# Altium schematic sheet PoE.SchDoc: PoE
size A4; CompanyName: STMicroelectronics; Organization: Microcontrollers Division; DocumentNumber: 13; SheetNumber: 6; SheetTotal: 19
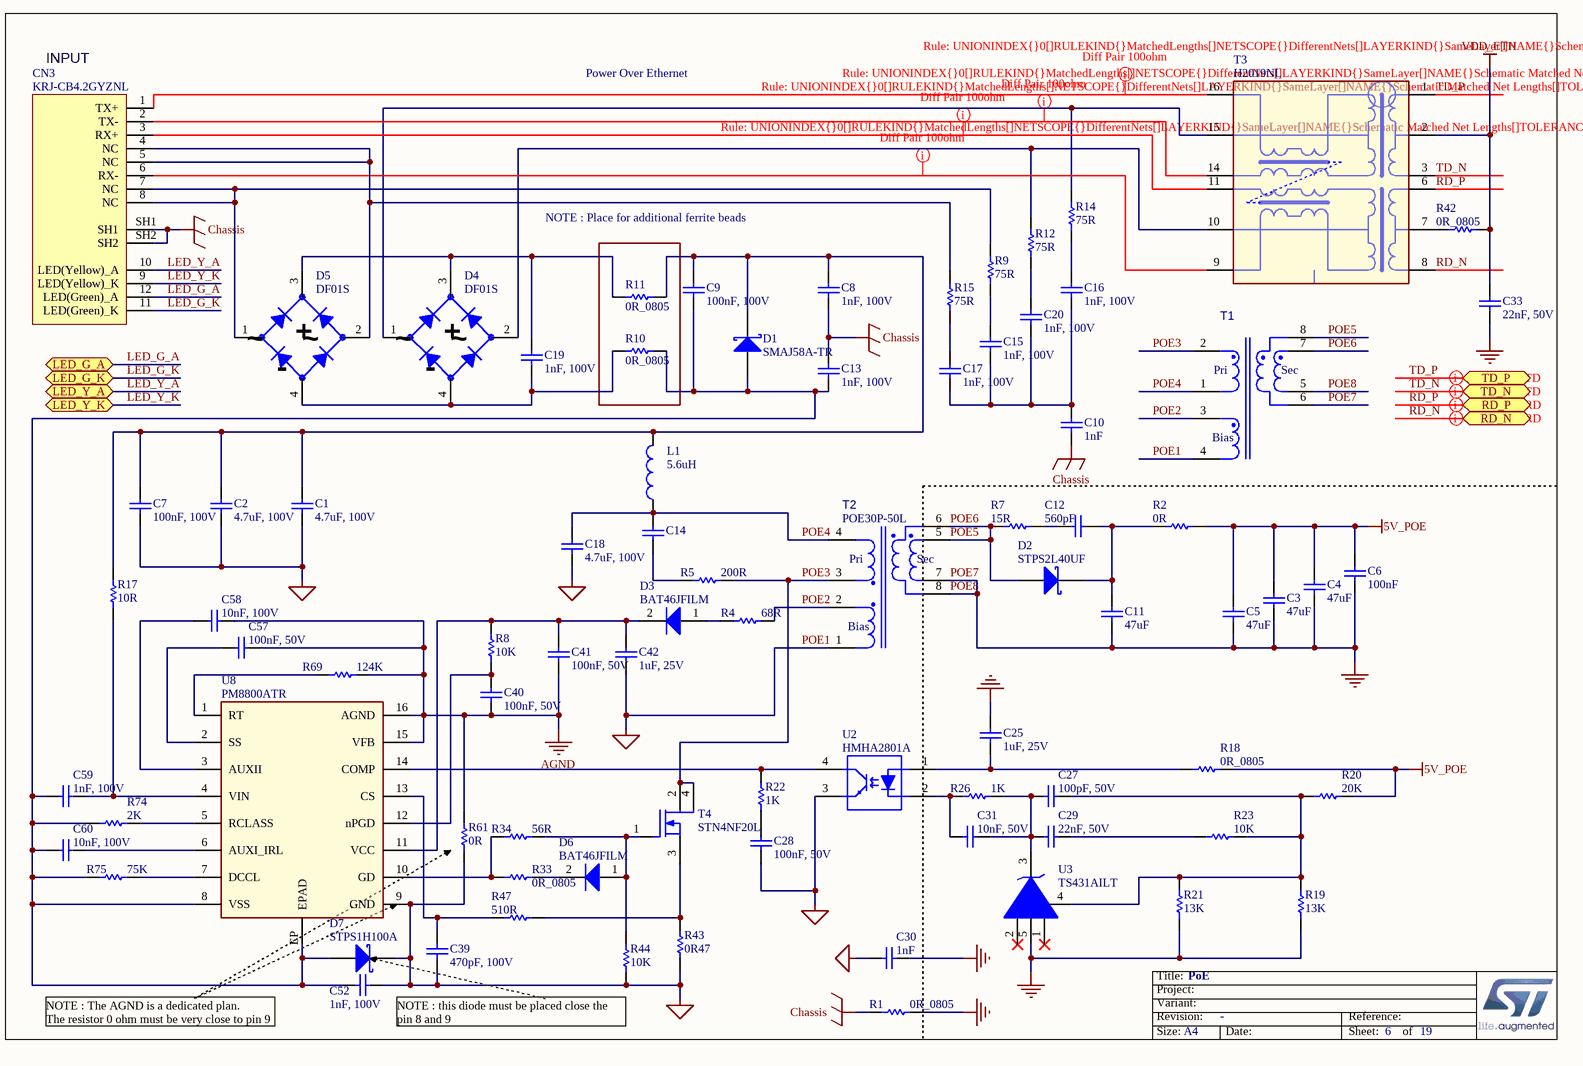
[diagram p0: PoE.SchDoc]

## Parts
C1  value 4.7uF, 100V  [C1210]  (hidden comment: Capacitor)
C2  value 4.7uF, 100V  [C1210]  (hidden comment: Capacitor)
C3  value 47uF  [C0805]  (hidden comment: Capacitor)
C4  value 47uF  [C0805]  (hidden comment: Capacitor)
C5  value 47uF  [C0805]  (hidden comment: Capacitor)
C6  value 100nF  [C0603]  (hidden comment: Capacitor)
C7  value 100nF, 100V  [C0805]  (hidden comment: Capacitor)
C8  value 1nF, 100V  [C0603]  (hidden comment: Capacitor)
C9  value 100nF, 100V  [C0805]  (hidden comment: Capacitor)
C10  value 1nF  [C1206_H1P6]  (hidden comment: Capacitor)
C11  value 47uF  [C0805]  (hidden comment: Capacitor)
C12  value 560pF  [C0603]  (hidden comment: Capacitor)
C13  value 1nF, 100V  [C0603]  (hidden comment: Capacitor)
C14  Capacitor  [C0603]  (value not drawn)
C15  value 1nF, 100V  [C0603]  (hidden comment: Capacitor)
C16  value 1nF, 100V  [C0603]  (hidden comment: Capacitor)
C17  value 1nF, 100V  [C0603]  (hidden comment: Capacitor)
C18  value 4.7uF, 100V  [C1210]  (hidden comment: Capacitor)
C19  value 1nF, 100V  [C0603]  (hidden comment: Capacitor)
C20  value 1nF, 100V  [C0603]  (hidden comment: Capacitor)
C25  value 1uF, 25V  [C0603]  (hidden comment: Capacitor)
C27  value 100pF, 50V  [C0603]  (hidden comment: Capacitor)
C28  value 100nF, 50V  [C0603]  (hidden comment: Capacitor)
C29  value 22nF, 50V  [C0603]  (hidden comment: Capacitor)
C30  value 1nF  [C1206_H1P6]  (hidden comment: Capacitor)
C31  value 10nF, 50V  [C0603]  (hidden comment: Capacitor)
C33  value 22nF, 50V  [C0603]  (hidden comment: Capacitor)
C39  value 470pF, 100V  [C0603]  (hidden comment: Capacitor)
C40  value 100nF, 50V  [C0603]  (hidden comment: Capacitor)
C41  value 100nF, 50V  [C0603]  (hidden comment: Capacitor)
C42  value 1uF, 25V  [C0603]  (hidden comment: Capacitor)
C52  value 1nF, 100V  [C0603]  (hidden comment: Capacitor)
C57  value 100nF, 50V  [C0603]  (hidden comment: Capacitor)
C58  value 10nF, 100V  [C0603]  (hidden comment: Capacitor)
C59  value 1nF, 100V  [C0603]  (hidden comment: Capacitor)
C60  value 10nF, 100V  [C0603]  (hidden comment: Capacitor)
CN3  value KRJ-CB4.2GYZNL  [CON_RJ45_DGKYD_KRJ-CB4.2GYZNL]  (hidden comment: RJ45_KRJ-CB4.2GYZNL)
D1  SMAJ58A-TR  [DIO_SMA_1A_2K]
D2  STPS2L40UF  [DIO_SMB-FLAT_1A_2K]
D3  value BAT46JFILM  [DIO_SOD323_1A_2K]  (hidden comment: DIODE_1A_2K)
D4  DF01S  [BRF_VISHAY_DFS_DF01S]
D5  DF01S  [BRF_VISHAY_DFS_DF01S]
D6  value BAT46JFILM  [DIO_SOD323_1A_2K]  (hidden comment: DIODE_1A_2K)
D7  value STPS1H100A  [DIO_SMA_DO214-AC_1A_2K]  (hidden comment: SMAJ58A-TR)
L1  value 5.6uH  [IND_POWER_COILCRAFT_ME3220]  (hidden comment: Inductor)
R1  value 0R_0805  [R0805]  (hidden comment: Resistor)
R2  value 0R  [R0603]  (hidden comment: Resistor)
R4  value 68R  [R0805]  (hidden comment: Resistor)
R5  value 200R  [R1206_H0P55]  (hidden comment: Resistor)
R7  value 15R  [R0805]  (hidden comment: Resistor)
R8  value 10K  [R0603]  (hidden comment: Resistor)
R9  value 75R  [R0805]  (hidden comment: Resistor)
R10  value 0R_0805  [R0805]  (hidden comment: Resistor)
R11  value 0R_0805  [R0805]  (hidden comment: Resistor)
R12  value 75R  [R0805]  (hidden comment: Resistor)
R14  value 75R  [R0805]  (hidden comment: Resistor)
R15  value 75R  [R0805]  (hidden comment: Resistor)
R17  value 10R  [R0805]  (hidden comment: Resistor)
R18  value 0R_0805  [R0805]  (hidden comment: Resistor)
R19  value 13K  [R0603]  (hidden comment: Resistor)
R20  value 20K  [R0603]  (hidden comment: Resistor)
R21  value 13K  [R0603]  (hidden comment: Resistor)
R22  value 1K  [R0603]  (hidden comment: Resistor)
R23  value 10K  [R0603]  (hidden comment: Resistor)
R26  value 1K  [R0603]  (hidden comment: Resistor)
R33  value 0R_0805  [R0805]  (hidden comment: Resistor)
R34  value 56R  [R0805]  (hidden comment: Resistor)
R42  value 0R_0805  [R0805]  (hidden comment: Resistor)
R43  value 0R47  [R1206_H0P55]  (hidden comment: Resistor)
R44  value 10K  [R0603]  (hidden comment: Resistor)
R47  value 510R  [R0603]  (hidden comment: Resistor)
R61  value 0R  [R0603]  (hidden comment: Resistor)
R69  value 124K  [R0603]  (hidden comment: Resistor)
R74  value 2K  [R0805]  (hidden comment: Resistor)
R75  value 75K  [R0603]  (hidden comment: Resistor)
T1  TRS_750315923  [TRS_WURTH_750315923]  (value not drawn)
T2  POE30P-50L  [TRS_COILCRAFT_POE30P-50L]
T3  H2019NL  [TRS_PULSE_H2019NL]
T4  STN4NF20L  [MOS_SOT223-TAB]
U2  HMHA2801A  [OPT_MINI-FLAT_FAIRCHILD_HMHA2801A]
U3  TS431AILT  [MOS_SOT23-5L]
U8  PM8800ATR  [ICC_HTSSOP16-EPAD_5X4P4_P065]

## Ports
LED_G_A, LED_G_K, LED_Y_A, LED_Y_K, RD_N, RD_P, TD_N, TD_P

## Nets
5V_POE: C3.2 C4.2 C5.2 C6.2 R2.2 R18.2 R20.2
AGND: C40.1 C41.1 C57.2 C58.2 R61.2 R69.2 U8.15(VFB) U8.16(AGND)
Chassis: C8.1 C10.1 C13.2 CN3.SH1 CN3.SH2 R1.1
POE1: C1.1 C2.1 C7.1 C18.1 C28.1 C30.1 C39.1 C42.1 C52.1 D7.2(K) R43.1 R44.1 R61.1 T1.4 T2.1 U2.3(Emitter) U8.9(GND)  [also labelled GND_POWER_IN]
POE7: C3.1 C4.1 C5.1 C6.1 C11.1 C25.2 C30.2 C33.1 R1.2 R19.2 R21.1 T1.5 T1.6 T2.7 T2.8 U3.5(A)  [also labelled GND, POE8]
VDD_ETH: C33.2 R42.2 T3.2(tct)
LED_G_A: CN3.12(LED(Green)_A) ; port LED_G_A
LED_G_K: CN3.11(LED(Green)_K) ; port LED_G_K
LED_Y_A: CN3.10(LED(Yellow)_A) ; port LED_Y_A
LED_Y_K: CN3.9(LED(Yellow)_K) ; port LED_Y_K
POE2: R4.2 T1.3 T2.2
POE3: R5.2 T1.2 T2.3 T4.2(D) T4.4(D)
POE4: C14.2 C18.2 L1.1 T1.1 T2.4
POE5: D2.1(A) R7.1 T1.7 T1.8 T2.5 T2.6  [also labelled POE6]
RD_N: T3.8(rd-) ; port RD_N
RD_P: T3.6(rd+) ; port RD_P
TD_N: T3.3(td-) ; port TD_N
TD_P: T3.1(td+) ; port TD_P
NetC1_2: C1.2 C2.2 C7.2 C8.2 C9.1 D1.2(K) L1.2 R11.2 R17.2
NetC9_2: C9.2 C13.1 C52.2 C59.2 C60.1 D1.1(A) D7.1(A) R10.2 R74.1 R75.1 U8.8(VSS) U8.EP(EPAD)
NetC10_2: C10.2 C15.1 C16.1 C17.1 C20.1
NetC11_2: C11.2 C12.2 D2.2(K) R2.1
NetC12_1: C12.1 R7.2
NetC14_1: C14.1 R5.1
NetC15_2: C15.2 R9.1
NetC16_2: C16.2 R14.1
NetC17_2: C17.2 R15.1
NetC19_1: C19.1 D4.4(DC_OUT_MINUS) D5.4(DC_OUT_MINUS) R10.1
NetC19_2: C19.2 D4.3(DC_OUT_PLUS) D5.3(DC_OUT_PLUS) R11.1
NetC20_2: C20.2 R12.1
NetC25_1: C25.1 R18.1 U2.1(Anode)
NetC27_1: C27.1 C29.1 C31.2 R26.1 U3.3(K)
NetC27_2: C27.2 R19.1 R20.1 R21.2 R23.1 U3.4(REF)
NetC28_2: C28.2 R22.1
NetC29_2: C29.2 R23.2
NetC31_1: C31.1 R26.2 U2.2(B)
NetC39_2: C39.2 R47.1 U8.13(CS)
NetC40_2: C40.2 R8.1 U8.12(nPGD)
NetC41_2: C41.2 C42.2 D3.2(K) R8.2 U8.11(VCC)
NetC57_1: C57.1 U8.2(SS)
NetC58_1: C58.1 U8.3(AUXII)
NetC59_1: C59.1 R17.1 U8.4(VIN)
NetC60_2: C60.2 U8.6(AUXI_IRL)
NetCN3_1: CN3.1(TX+) T3.16(tx1+)
NetCN3_2: CN3.2(TX-) T3.14(tx1-)
NetCN3_3: CN3.3(RX+) T3.11(rx1+)
NetCN3_4: CN3.4(NC) CN3.5(NC) D5.2(AC_IN_2) R15.2
NetCN3_6: CN3.6(RX-) T3.9(rx-)
NetCN3_7: CN3.7(NC) CN3.8(NC) D5.1(AC_IN_1) R9.2
NetD3_1: D3.1(A) R4.1
NetD4_1: D4.1(AC_IN_1) R14.2 T3.15(txct)
NetD4_2: D4.2(AC_IN_2) R12.2 T3.10(rxct)
NetD6_1: D6.1(A) R34.2 R44.2 T4.1(G)
NetD6_2: D6.2(K) R33.1
NetR22_2: R22.2 U2.4(Collector) U8.14(COMP)
NetR33_2: R33.2 R34.1 U8.10(GD)
NetR42_1: R42.1 T3.7(rct)
NetR43_2: R43.2 R47.2 T4.3(S)
NetR69_1: R69.1 U8.1(RT)
NetR74_2: R74.2 U8.5(RCLASS)
NetR75_2: R75.2 U8.7(DCCL)

Not connected (* = marked no-connect by the designer): U3 1(NC)* 2(NC)*

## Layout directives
differential pair: RD_N, RD_P, TD_N, TD_P
rule Matched Net Lengths [Tolerance = 100mil]: NetCN3_1, NetCN3_2, NetCN3_3, NetCN3_6

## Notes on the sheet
- INPUT
- Power Over Ethernet
- NOTE : Place for additional ferrite beads
- NOTE : The AGND is a dedicated plan.
  The resistor 0 ohm must be very close to pin 9
- NOTE : this diode must be placed close the pin 8 and 9

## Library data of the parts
C1 C2 C18 = MCD-01172: Capacitor,4.7uF,100V, X7S,20%,1210; Manufacturer_Part_Number: 12101Z475MAT2A; Manufacturer: AVX; Provided_By: SUBCO
C3-C5 C11 = MCD-00204: Capacitor, MLCC, 47uF, 10V, X5R, 20%, 0805, T=1,25mm; Manufacturer_Part_Number: GRM21BR61A476ME15K; Manufacturer: MURATA; Provided_By: SUBCO
C6 = MCD-00211: Capacitor, MLCC, 100nF, 16V, X7R, 10%, 0603, T=0,8mm; Manufacturer_Part_Number: CC0603KRX7R7BB104; Manufacturer: YAGEO; Provided_By: SUBCO
C7 C9 = MCD-01093: Capacitor,100nF,100V,X7R,10%,0805; Manufacturer_Part_Number: C2012X7R2A104K125AA; Manufacturer: TDK; Provided_By: SUBCO
C8 C13 C15-C17 C19 C20 C52 C59 = MCD-01091: Capacitor,1nF,100V,X7R,10%,0603; Manufacturer_Part_Number: CC0603KRX7R0BB102; Manufacturer: YAGEO; Provided_By: SUBCO
C10 C30 = MCD-00722: Capacitor, MLCC, 1nF, 2KV, X7R, 10%, 1206, T=1,25mm; Manufacturer_Part_Number: CC1206KKX7RDBB102; Manufacturer: YAGEO; Provided_By: SUBCO
C12 = MCD-01095: Capacitor,560pF,16V,X7R,10%,0603; Manufacturer_Part_Number: 0603YC561KAT2A; Manufacturer: AVX; Provided_By: SUBCO
C14 = MCD-01096: Capacitor,27pF,100V,NPO,5%,0603; Manufacturer_Part_Number: CC0603JRNPO0BN270; Manufacturer: YAGEO; Provided_By: SUBCO
C25 C42 = MCD-01100: Capacitor,1uF,25V,X5R,10%,0603; Manufacturer_Part_Number: CC0603KRX5R8BB105; Manufacturer: YAGEO; Provided_By: SUBCO
C27 = MCD-01101: Capacitor,100pF,50V,X7R,10%,0603; Manufacturer_Part_Number: 06035C101JAT4A; Manufacturer: AVX; Provided_By: SUBCO
C28 C40 C41 C57 = MCD-01099: Capacitor,100nF,50V,X7R,10%,0603; Manufacturer_Part_Number: CC0603KRX7R9BB104; Manufacturer: YAGEO; Provided_By: SUBCO
C29 C33 = MCD-01103: Capacitor,22nF,50V,X7R,10%,0603; Manufacturer_Part_Number: CC0603KRX7R9BB223; Manufacturer: YAGEO; Provided_By: SUBCO
C31 = MCD-01102: Capacitor,10nF,50V,X7R,10%,0603; Manufacturer_Part_Number: CC0603KRX7R9BB103; Manufacturer: YAGEO; Provided_By: SUBCO
C39 = MCD-01104: Capacitor,470pF,100V,X7R,10%,0603; Manufacturer_Part_Number: 06031C471KAT2A; Manufacturer: AVX; Provided_By: SUBCO
C58 C60 = MCD-01098: Capacitor,10nF,100V,X7R,10%,0603; Manufacturer_Part_Number: CC0603KRX7R0BB103; Manufacturer: YAGEO; Provided_By: SUBCO
CN3 = MCD-00717: RJ45 jack, single port, with LEDS, Metal shielded dip low profile; Part_Type: Connector; Manufacturer: DONGGUAN KEYOUDA ELECTRONIC TECHNOLOGY; Provided_By: SUBCO
D1 = MCD-01083: Transil 400W, VRM=58V; Part_Type: Diode; Manufacturer: STMICROELECTRONICS; BMS_Part_Number: 9151124; Provided_By: SUBCO with ST control
D2 = MCD-01087: Low drop power Schottky rectifier(2A, 40V, 0.34V); Part_Type: Diode; Manufacturer: STMICROELECTRONICS; BMS_Part_Number: 9151009; Provided_By: SUBCO with ST control
D3 D6 = MCD-01064: Schottky Single diode,150mA, 100V; Manufacturer: STMICROELECTRONICS; BMS_Part_Number: 9151125; Provided_By: SUBCO with ST control
D4 D5 = MCD-01065: Surface Mount Bridge Rectifiers; Part_Type: IC; Manufacturer: VISHAY; Provided_By: SUBCO
D7 = MCD-01165: High voltage power Schottky rectifier; Part_Type: Diode; Manufacturer: STMICROELECTRONICS; BMS_Part_Number: 9151102; Provided_By: SUBCO with ST control
L1 = MCD-01109: Power Inductor, 5.6uH, 0.2R, ME3220-562ML; Manufacturer: COILCRAFT; Provided_By: SUBCO
R1 R10 R11 R18 R33 R42 = MCD-00179: Resistor,0R,0805,5%; Manufacturer_Part_Number: RC0805JR-070RL; Manufacturer: YAGEO; Provided_By: SUBCO
R2 R61 = MCD-00056: Resistor,0R,0603,5%,1/10W; Manufacturer_Part_Number: RC0603JR-070RL; Manufacturer: YAGEO; Provided_By: SUBCO
R4 = MCD-01115: Resistor,68R,0805,1%; Manufacturer_Part_Number: RC0805FR-0768RL; Manufacturer: YAGEO; Provided_By: SUBCO
R5 = MCD-01114: Resistor,200R,1206,1%; Manufacturer_Part_Number: LTR18EZPF2000; Manufacturer: ROHM; Provided_By: SUBCO
R7 = MCD-01113: Resistor,15R,0805,1%; Manufacturer_Part_Number: RC0805FR-0715RL; Manufacturer: YAGEO; Provided_By: SUBCO
R8 R23 R44 = MCD-00220: Resistor,10K,0603,1%,1/10W; Manufacturer_Part_Number: RC0603FR-0710KL; Manufacturer: YAGEO; Provided_By: SUBCO
R9 R12 R14 R15 = MCD-01112: Resistor,75R,0805,1%; Manufacturer_Part_Number: RC0805FR-0775RL; Manufacturer: YAGEO; Provided_By: SUBCO
R17 = MCD-01111: Resistor,10R,0805,1%,Stackpole,1/4W; Manufacturer_Part_Number: RNCP0805FTD10R0; Provided_By: SUBCO
R19 R21 = MCD-00384: Resistor,13K,0603,1%,1/10W; Manufacturer_Part_Number: RC0603FR-0713KL; Manufacturer: YAGEO; Provided_By: SUBCO
R20 = MCD-00422: Resistor,20K,0603,1%,1/10W; Manufacturer_Part_Number: RC0603FR-0720KL; Manufacturer: YAGEO; Provided_By: SUBCO
R22 R26 = MCD-00070: Resistor,1K,0603,1%,1/10W; Manufacturer_Part_Number: RC0603FR-071KL; Manufacturer: YAGEO; Provided_By: SUBCO
R34 = MCD-01118: Resistor,56R,0805,1%; Manufacturer_Part_Number: RC0805FR-0756RL; Manufacturer: YAGEO; Provided_By: SUBCO
R43 = MCD-01119: Resistor,0.47R,1206,1%; Manufacturer_Part_Number: RL1206FR-070R47L; Manufacturer: YAGEO; Provided_By: SUBCO
R47 = MCD-00225: Resistor,510R,0603,1%,1/10W; Manufacturer_Part_Number: RC0603FR-07510RL; Manufacturer: YAGEO; Provided_By: SUBCO
R69 = MCD-01116: Resistor,124K,0603,1%; Manufacturer_Part_Number: RC0603FR-07124KL; Manufacturer: YAGEO; Provided_By: SUBCO
R74 = MCD-01117: Resistor,2K,0805,1%; Manufacturer_Part_Number: RC0805FR-072KL; Manufacturer: YAGEO; Provided_By: SUBCO
R75 = MCD-00522: Resistor,75K,0603,1%,1/10W; Manufacturer_Part_Number: RC0603FR-0775KL; Manufacturer: YAGEO; Provided_By: SUBCO
T1 = MCD-01063: Flyback Transformers for 3 Watt, PoE applications; Part_Type: IC; Manufacturer: WURTH; Provided_By: SUBCO
T2 = MCD-01081: Flyback Transformers for 3 Watt, PoE applications, CoilCraft Cyntec; Part_Type: IC; Provided_By: SUBCO
T3 = MCD-01067: 10/100BASE-TX VoIP Magnetics Modules, Data Transformer; Part_Type: IC; Manufacturer: PULSE; Provided_By: SUBCO
T4 = MCD-01086: Annel 200 V, 1.1ohm, 1 A, low gate charge STripFET II, Power MOSFET; Part_Type: IC; Manufacturer: STMICROELECTRONICS; BMS_Part_Number: 9153018; Provided_By: SUBCO with ST control
U2 = MCD-01068: OPTOISOLATOR 3.7KV TRANSISTOR 4SMD; Part_Type: IC; Manufacturer: FAIRCHILD; Provided_By: SUBCO
U3 = MCD-01089: Low voltage adjustable shunt reference; Part_Type: IC; Manufacturer: STMICROELECTRONICS; BMS_Part_Number: 9177032; Provided_By: SUBCO with ST control
U8 = MCD-01080: Integrated IEEE 802.3af compliant PoE-PD interface, and PWM controller with support of external source; Part_Type: IC; Manufacturer: STMICROELECTRONICS; BMS_Part_Number: 9177966; Provided_By: SUBCO with ST control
